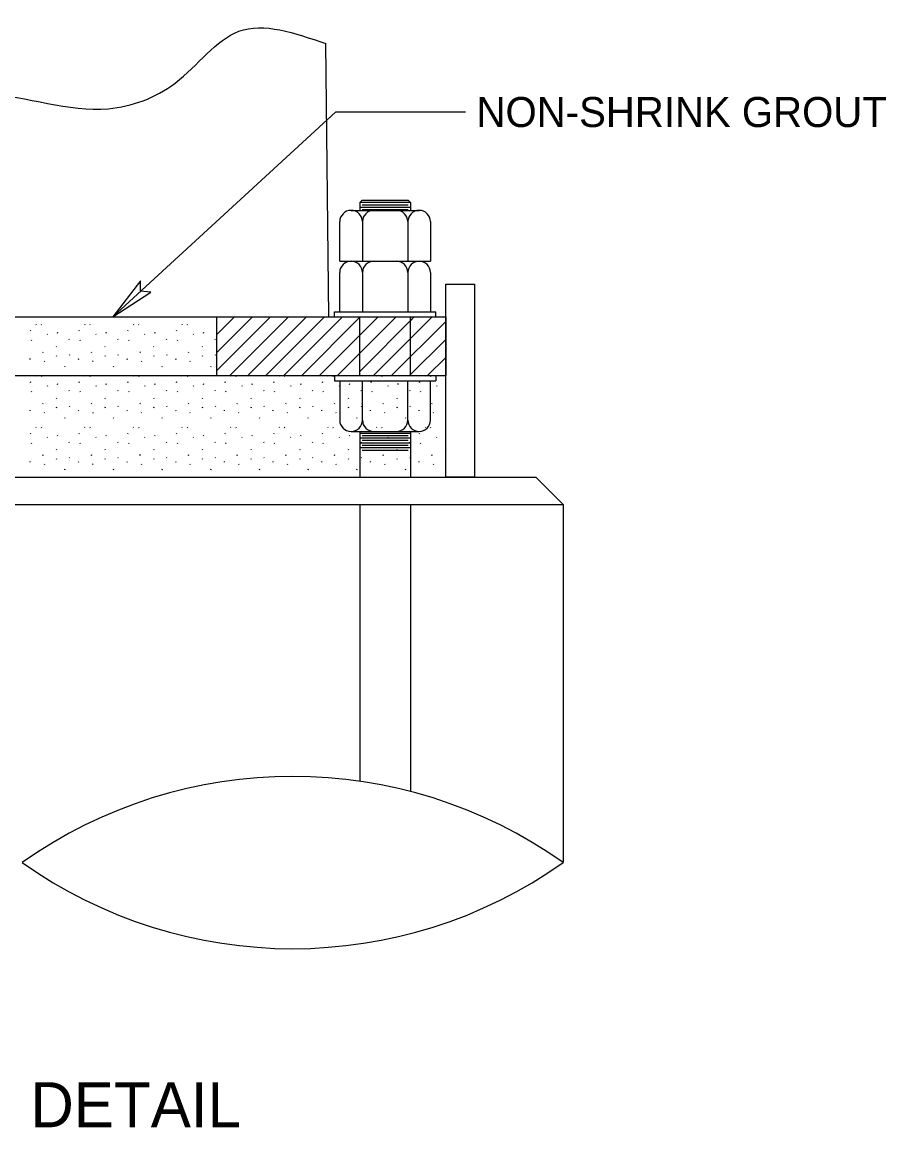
# Model space of a CAD drawing. Extents: x 99978 to 113378, y 99891 to 102182.
# Drawn here: x 111348.5 to 111693.8, y 100709.4 to 101151.3 of the extents above; entities that cross this region are included whole.
import ezdxf

# ---------------------------------------------------------------- set-up
doc = ezdxf.new("R2010")
doc.units = 0
doc.layers.add('Border Organizer Shape', color=7, linetype='Continuous')

msp = doc.modelspace()

# ---------------------------------------------------------------- linework, layer by layer
at = {"layer": 'Border Organizer Shape'}
for p, q in [((111471.07, 101033.49), (111469.85, 101142.75)), ((111473.79, 101115.41), (111384.79, 101033.49)), ((111525.69, 101115.41), (111473.79, 101115.41)), ((111484.44, 101080.15), (111483.47, 101079.18)), ((111483.47, 101079.18), (111483.47, 101076.09)), ((111503.75, 101079.18), (111483.47, 101079.18)), ((111484.44, 101080.15), (111502.78, 101080.15)), ((111502.78, 101078.2), (111484.44, 101078.2)), ((111503.75, 101079.18), (111502.78, 101080.15)), ((111503.75, 101079.18), (111503.75, 101076.09)), ((111479.98, 101076.09), (111507.24, 101076.09)), ((111503.75, 101077.23), (111483.47, 101077.23)), ((111502.78, 101076.26), (111484.44, 101076.26)), ((111475.47, 101055.81), (111475.47, 101071.59)), ((111484.54, 101071.59), (111484.54, 101055.81)), ((111502.68, 101071.59), (111502.68, 101055.81)), ((111511.74, 101071.59), (111511.74, 101055.81)), ((111475.47, 101055.81), (111511.74, 101055.81)), ((111479.98, 101055.81), (111507.24, 101055.81)), ((111475.47, 101035.52), (111475.47, 101051.3)), ((111484.54, 101051.3), (111484.54, 101035.52)), ((111502.68, 101051.3), (111502.68, 101035.52)), ((111511.74, 101051.3), (111511.74, 101035.52)), ((111473.32, 101035.52), (111513.89, 101035.52)), ((111473.32, 101033.49), (111473.32, 101035.52)), ((111475.47, 101035.52), (111511.74, 101035.52)), ((111513.89, 101033.49), (111513.89, 101035.52)), ((111179.13, 101033.49), (111517.82, 101033.49)), ((111354, 101030.62), (111354.14, 101030.41)), ((111356.08, 101030.54), (111356.22, 101030.32)), ((111373.44, 101030.62), (111373.59, 101030.41)), ((111375.52, 101030.54), (111375.67, 101030.32)), ((111392.89, 101030.62), (111393.03, 101030.41)), ((111394.97, 101030.54), (111395.12, 101030.32)), ((111412.33, 101030.62), (111412.48, 101030.41)), ((111414.42, 101030.54), (111414.56, 101030.32)), ((111426.19, 101033.49), (111426.19, 101033.49)), ((111426.19, 101026.31), (111433.37, 101033.49)), ((111426.19, 101019.12), (111440.56, 101033.49)), ((111426.19, 101011.93), (111447.75, 101033.49)), ((111426.19, 101033.49), (111426.19, 101010.06)), ((111431.5, 101010.06), (111454.94, 101033.49)), ((111438.69, 101010.06), (111462.12, 101033.49)), ((111445.87, 101010.06), (111469.31, 101033.49)), ((111453.06, 101010.06), (111476.5, 101033.49)), ((111460.25, 101010.06), (111483.68, 101033.49)), ((111467.43, 101010.06), (111490.87, 101033.49)), ((111473.32, 101033.49), (111513.89, 101033.49)), ((111474.62, 101010.06), (111498.06, 101033.49)), ((111505.25, 101033.49), (111483.47, 101011.72)), ((111483.47, 101010.06), (111483.47, 101033.49)), ((111489, 101010.06), (111512.43, 101033.49)), ((111496.18, 101010.06), (111517.82, 101031.7)), ((111503.75, 101032), (111505.25, 101033.49)), ((111503.75, 101010.06), (111503.75, 101033.49)), ((111517.82, 101033.49), (111517.82, 101010.06)), ((111351.84, 101027.91), (111351.99, 101028.24)), ((111358.53, 101026.65), (111358.68, 101026.43)), ((111362.62, 101027.07), (111362.77, 101027.4)), ((111371.29, 101027.91), (111371.43, 101028.24)), ((111377.98, 101026.65), (111378.12, 101026.43)), ((111382.07, 101027.07), (111382.21, 101027.4)), ((111390.73, 101027.91), (111390.88, 101028.24)), ((111397.42, 101026.65), (111397.57, 101026.43)), ((111401.51, 101027.07), (111401.66, 101027.4)), ((111410.18, 101027.91), (111410.32, 101028.24)), ((111416.87, 101026.65), (111417.01, 101026.43)), ((111420.96, 101027.07), (111421.11, 101027.4)), ((111352.07, 101024.34), (111352.21, 101024.12)), ((111362.14, 101021.74), (111362.28, 101021.52)), ((111367.19, 101024.74), (111367.34, 101024.52)), ((111371.51, 101024.34), (111371.66, 101024.12)), ((111381.58, 101021.74), (111381.73, 101021.52)), ((111386.64, 101024.74), (111386.78, 101024.52)), ((111390.96, 101024.34), (111391.1, 101024.12)), ((111401.03, 101021.74), (111401.17, 101021.52)), ((111406.08, 101024.74), (111406.23, 101024.52)), ((111410.4, 101024.34), (111410.55, 101024.12)), ((111420.47, 101021.74), (111420.62, 101021.52)), ((111425.53, 101024.74), (111425.68, 101024.52)), ((111503.37, 101010.06), (111517.82, 101024.51)), ((111351.5, 101016.87), (111351.54, 101016.54)), ((111356.7, 101019.29), (111356.85, 101019.62)), ((111362.26, 101017.79), (111362.4, 101018.12)), ((111367.33, 101018.5), (111367.47, 101018.28)), ((111370.95, 101016.87), (111370.98, 101016.54)), ((111376.15, 101019.29), (111376.29, 101019.62)), ((111381.7, 101017.79), (111381.85, 101018.12)), ((111386.77, 101018.5), (111386.92, 101018.28)), ((111390.39, 101016.87), (111390.43, 101016.54)), ((111395.59, 101019.29), (111395.74, 101019.62)), ((111401.15, 101017.79), (111401.29, 101018.12)), ((111406.22, 101018.5), (111406.37, 101018.28)), ((111409.84, 101016.87), (111409.88, 101016.54)), ((111415.04, 101019.29), (111415.18, 101019.62)), ((111420.59, 101017.79), (111420.74, 101018.12)), ((111425.67, 101018.5), (111425.81, 101018.28)), ((111510.56, 101010.06), (111517.82, 101017.32)), ((111357.23, 101015.9), (111357.38, 101015.68)), ((111365.58, 101013.55), (111365.73, 101013.88)), ((111376.68, 101015.9), (111376.82, 101015.68)), ((111385.03, 101013.55), (111385.18, 101013.88)), ((111396.12, 101015.9), (111396.27, 101015.68)), ((111404.48, 101013.55), (111404.62, 101013.88)), ((111415.57, 101015.9), (111415.72, 101015.68)), ((111423.92, 101013.55), (111424.07, 101013.88)), ((111270.76, 101010.06), (111426.19, 101010.06)), ((111351.84, 101007.35), (111351.99, 101007.68)), ((111354, 101010.06), (111354.14, 101009.84)), ((111356.08, 101009.97), (111356.22, 101009.75)), ((111371.29, 101007.35), (111371.43, 101007.68)), ((111373.44, 101010.06), (111373.59, 101009.84)), ((111375.52, 101009.97), (111375.67, 101009.75)), ((111390.73, 101007.35), (111390.88, 101007.68)), ((111392.89, 101010.06), (111393.03, 101009.84)), ((111394.97, 101009.97), (111395.12, 101009.75)), ((111410.18, 101007.35), (111410.32, 101007.68)), ((111412.33, 101010.06), (111412.48, 101009.84)), ((111414.42, 101009.97), (111414.56, 101009.75)), ((111426.19, 101010.06), (111517.82, 101010.06)), ((111429.62, 101007.35), (111429.77, 101007.68)), ((111431.78, 101010.06), (111431.93, 101009.84)), ((111433.86, 101009.97), (111434.01, 101009.75)), ((111441.84, 101010.06), (111517.82, 101010.06)), ((111449.07, 101007.35), (111449.22, 101007.68)), ((111451.23, 101010.06), (111451.37, 101009.84)), ((111453.31, 101009.97), (111453.45, 101009.75)), ((111468.52, 101007.35), (111468.66, 101007.68)), ((111470.67, 101010.06), (111470.82, 101009.84)), ((111472.75, 101009.97), (111472.9, 101009.75)), ((111473.32, 101010.06), (111513.89, 101010.06)), ((111473.32, 101010.06), (111473.32, 101008.03)), ((111473.32, 101008.03), (111513.89, 101008.03)), ((111475.47, 101008.03), (111511.74, 101008.03)), ((111475.47, 101008.03), (111475.47, 100992.25)), ((111484.54, 100992.25), (111484.54, 101008.03)), ((111487.96, 101007.35), (111488.11, 101007.68)), ((111490.12, 101010.06), (111490.27, 101009.84)), ((111492.2, 101009.97), (111492.35, 101009.75)), ((111502.68, 100992.25), (111502.68, 101008.03)), ((111507.41, 101007.35), (111507.55, 101007.68)), ((111509.57, 101010.06), (111509.71, 101009.84)), ((111511.65, 101009.97), (111511.79, 101009.75)), ((111511.74, 100992.25), (111511.74, 101008.03)), ((111513.89, 101010.06), (111513.89, 101008.03)), ((111517.74, 101010.06), (111517.82, 101010.14)), ((111352.07, 101003.77), (111352.21, 101003.55)), ((111358.53, 101006.08), (111358.68, 101005.86)), ((111362.62, 101006.51), (111362.77, 101006.84)), ((111367.19, 101004.17), (111367.34, 101003.95)), ((111371.51, 101003.77), (111371.66, 101003.55)), ((111377.98, 101006.08), (111378.12, 101005.86)), ((111382.07, 101006.51), (111382.21, 101006.84)), ((111386.64, 101004.17), (111386.78, 101003.95)), ((111390.96, 101003.77), (111391.1, 101003.55)), ((111397.42, 101006.08), (111397.57, 101005.86)), ((111401.51, 101006.51), (111401.66, 101006.84)), ((111406.08, 101004.17), (111406.23, 101003.95)), ((111410.4, 101003.77), (111410.55, 101003.55)), ((111416.87, 101006.08), (111417.01, 101005.86)), ((111420.96, 101006.51), (111421.11, 101006.84)), ((111425.53, 101004.17), (111425.68, 101003.95)), ((111429.85, 101003.77), (111430, 101003.55)), ((111436.31, 101006.08), (111436.46, 101005.86)), ((111440.41, 101006.51), (111440.55, 101006.84)), ((111444.98, 101004.17), (111445.12, 101003.95)), ((111449.3, 101003.77), (111449.44, 101003.55)), ((111455.76, 101006.08), (111455.91, 101005.86)), ((111459.85, 101006.51), (111460, 101006.84)), ((111464.42, 101004.17), (111464.57, 101003.95)), ((111468.74, 101003.77), (111468.89, 101003.55)), ((111475.21, 101006.08), (111475.35, 101005.86)), ((111479.3, 101006.51), (111479.44, 101006.84)), ((111483.87, 101004.17), (111484.01, 101003.95)), ((111488.19, 101003.77), (111488.33, 101003.55)), ((111494.65, 101006.08), (111494.8, 101005.86)), ((111498.74, 101006.51), (111498.89, 101006.84)), ((111503.31, 101004.17), (111503.46, 101003.95)), ((111507.63, 101003.77), (111507.78, 101003.55)), ((111514.1, 101006.08), (111514.25, 101005.86)), ((111356.7, 100998.72), (111356.85, 100999.05)), ((111362.14, 101001.18), (111362.28, 101000.96)), ((111376.15, 100998.72), (111376.29, 100999.05)), ((111381.58, 101001.18), (111381.73, 101000.96)), ((111395.59, 100998.72), (111395.74, 100999.05)), ((111401.03, 101001.18), (111401.17, 101000.96)), ((111415.04, 100998.72), (111415.18, 100999.05)), ((111420.47, 101001.18), (111420.62, 101000.96)), ((111434.48, 100998.72), (111434.63, 100999.05)), ((111439.92, 101001.18), (111440.07, 101000.96)), ((111453.93, 100998.72), (111454.08, 100999.05)), ((111459.37, 101001.18), (111459.51, 101000.96)), ((111473.38, 100998.72), (111473.52, 100999.05)), ((111478.81, 101001.18), (111478.96, 101000.96)), ((111492.82, 100998.72), (111492.97, 100999.05)), ((111498.26, 101001.18), (111498.41, 101000.96)), ((111512.27, 100998.72), (111512.42, 100999.05)), ((111517.71, 101001.18), (111517.82, 101001)), ((111351.5, 100996.3), (111351.54, 100995.97)), ((111357.23, 100995.33), (111357.38, 100995.11)), ((111362.26, 100997.22), (111362.4, 100997.55)), ((111367.33, 100997.93), (111367.47, 100997.71)), ((111370.95, 100996.3), (111370.98, 100995.97)), ((111376.68, 100995.33), (111376.82, 100995.11)), ((111381.7, 100997.22), (111381.85, 100997.55)), ((111386.77, 100997.93), (111386.92, 100997.71)), ((111390.39, 100996.3), (111390.43, 100995.97)), ((111396.12, 100995.33), (111396.27, 100995.11)), ((111401.15, 100997.22), (111401.29, 100997.55)), ((111406.22, 100997.93), (111406.37, 100997.71)), ((111409.84, 100996.3), (111409.88, 100995.97)), ((111415.57, 100995.33), (111415.72, 100995.11)), ((111420.59, 100997.22), (111420.74, 100997.55)), ((111425.67, 100997.93), (111425.81, 100997.71)), ((111429.29, 100996.3), (111429.32, 100995.97)), ((111435.02, 100995.33), (111435.16, 100995.11)), ((111440.04, 100997.22), (111440.19, 100997.55)), ((111445.11, 100997.93), (111445.26, 100997.71)), ((111448.73, 100996.3), (111448.77, 100995.97)), ((111454.46, 100995.33), (111454.61, 100995.11)), ((111459.49, 100997.22), (111459.63, 100997.55)), ((111464.56, 100997.93), (111464.71, 100997.71)), ((111468.18, 100996.3), (111468.21, 100995.97)), ((111473.91, 100995.33), (111474.05, 100995.11)), ((111478.93, 100997.22), (111479.08, 100997.55)), ((111484.01, 100997.93), (111484.15, 100997.71)), ((111487.62, 100996.3), (111487.66, 100995.97)), ((111493.35, 100995.33), (111493.5, 100995.11)), ((111498.38, 100997.22), (111498.53, 100997.55)), ((111503.45, 100997.93), (111503.6, 100997.71)), ((111507.07, 100996.3), (111507.11, 100995.97)), ((111512.8, 100995.33), (111512.95, 100995.11)), ((111365.58, 100992.98), (111365.73, 100993.31)), ((111385.03, 100992.98), (111385.18, 100993.31)), ((111404.48, 100992.98), (111404.62, 100993.31)), ((111423.92, 100992.98), (111424.07, 100993.31)), ((111443.37, 100992.98), (111443.51, 100993.31)), ((111462.81, 100992.98), (111462.96, 100993.31)), ((111482.26, 100992.98), (111482.41, 100993.31)), ((111501.71, 100992.98), (111501.85, 100993.31)), ((111351.84, 100986.78), (111351.99, 100987.11)), ((111354, 100989.49), (111354.14, 100989.27)), ((111356.08, 100989.41), (111356.22, 100989.19)), ((111358.53, 100985.51), (111358.68, 100985.29)), ((111362.62, 100985.94), (111362.77, 100986.27)), ((111371.29, 100986.78), (111371.43, 100987.11)), ((111373.44, 100989.49), (111373.59, 100989.27)), ((111375.52, 100989.41), (111375.67, 100989.19)), ((111377.98, 100985.51), (111378.12, 100985.29)), ((111382.07, 100985.94), (111382.21, 100986.27)), ((111390.73, 100986.78), (111390.88, 100987.11)), ((111392.89, 100989.49), (111393.03, 100989.27)), ((111394.97, 100989.41), (111395.12, 100989.19)), ((111397.42, 100985.51), (111397.57, 100985.29)), ((111401.51, 100985.94), (111401.66, 100986.27)), ((111410.18, 100986.78), (111410.32, 100987.11)), ((111412.33, 100989.49), (111412.48, 100989.27)), ((111414.42, 100989.41), (111414.56, 100989.19)), ((111416.87, 100985.51), (111417.01, 100985.29)), ((111420.96, 100985.94), (111421.11, 100986.27)), ((111429.62, 100986.78), (111429.77, 100987.11)), ((111431.78, 100989.49), (111431.93, 100989.27)), ((111433.86, 100989.41), (111434.01, 100989.19)), ((111436.31, 100985.51), (111436.46, 100985.29)), ((111440.41, 100985.94), (111440.55, 100986.27)), ((111449.07, 100986.78), (111449.22, 100987.11)), ((111451.23, 100989.49), (111451.37, 100989.27)), ((111453.31, 100989.41), (111453.45, 100989.19)), ((111455.76, 100985.51), (111455.91, 100985.29)), ((111459.85, 100985.94), (111460, 100986.27)), ((111468.52, 100986.78), (111468.66, 100987.11)), ((111470.67, 100989.49), (111470.82, 100989.27)), ((111472.75, 100989.41), (111472.9, 100989.19)), ((111475.21, 100985.51), (111475.35, 100985.29)), ((111479.3, 100985.94), (111479.44, 100986.27)), ((111479.98, 100987.74), (111507.24, 100987.74)), ((111483.47, 100987.74), (111483.47, 100969.49)), ((111503.75, 100986.97), (111483.47, 100986.97)), ((111502.78, 100986), (111484.44, 100986)), ((111487.96, 100986.78), (111488.11, 100987.11)), ((111490.12, 100989.49), (111490.27, 100989.27)), ((111492.2, 100989.41), (111492.35, 100989.19)), ((111494.65, 100985.51), (111494.8, 100985.29)), ((111498.74, 100985.94), (111498.89, 100986.27)), ((111503.75, 100987.74), (111503.75, 100969.49)), ((111507.41, 100986.78), (111507.55, 100987.11)), ((111509.57, 100989.49), (111509.71, 100989.27)), ((111511.65, 100989.41), (111511.79, 100989.19)), ((111514.1, 100985.51), (111514.25, 100985.29)), ((111352.07, 100983.2), (111352.21, 100982.98)), ((111367.19, 100983.6), (111367.34, 100983.38)), ((111371.51, 100983.2), (111371.66, 100982.98)), ((111386.64, 100983.6), (111386.78, 100983.38)), ((111390.96, 100983.2), (111391.1, 100982.98)), ((111406.08, 100983.6), (111406.23, 100983.38)), ((111410.4, 100983.2), (111410.55, 100982.98)), ((111425.53, 100983.6), (111425.68, 100983.38)), ((111429.85, 100983.2), (111430, 100982.98)), ((111444.98, 100983.6), (111445.12, 100983.38)), ((111449.3, 100983.2), (111449.44, 100982.98)), ((111464.42, 100983.6), (111464.57, 100983.38)), ((111468.74, 100983.2), (111468.89, 100982.98)), ((111503.75, 100985.03), (111483.47, 100985.03)), ((111503.75, 100983.08), (111483.47, 100983.08)), ((111503.75, 100981.13), (111483.47, 100981.13)), ((111483.87, 100983.6), (111484.01, 100983.38)), ((111502.78, 100984.05), (111484.44, 100984.05)), ((111502.78, 100982.1), (111484.44, 100982.1)), ((111488.19, 100983.2), (111488.33, 100982.98)), ((111503.31, 100983.6), (111503.46, 100983.38)), ((111507.63, 100983.2), (111507.78, 100982.98)), ((111356.7, 100978.15), (111356.85, 100978.48)), ((111362.14, 100980.61), (111362.28, 100980.39)), ((111362.26, 100976.65), (111362.4, 100976.98)), ((111367.33, 100977.36), (111367.47, 100977.14)), ((111376.15, 100978.15), (111376.29, 100978.48)), ((111381.58, 100980.61), (111381.73, 100980.39)), ((111381.7, 100976.65), (111381.85, 100976.98)), ((111386.77, 100977.36), (111386.92, 100977.14)), ((111395.59, 100978.15), (111395.74, 100978.48)), ((111401.03, 100980.61), (111401.17, 100980.39)), ((111401.15, 100976.65), (111401.29, 100976.98)), ((111406.22, 100977.36), (111406.37, 100977.14)), ((111415.04, 100978.15), (111415.18, 100978.48)), ((111420.47, 100980.61), (111420.62, 100980.39)), ((111420.59, 100976.65), (111420.74, 100976.98)), ((111425.67, 100977.36), (111425.81, 100977.14)), ((111434.48, 100978.15), (111434.63, 100978.48)), ((111439.92, 100980.61), (111440.07, 100980.39)), ((111440.04, 100976.65), (111440.19, 100976.98)), ((111445.11, 100977.36), (111445.26, 100977.14)), ((111453.93, 100978.15), (111454.08, 100978.48)), ((111459.37, 100980.61), (111459.51, 100980.39)), ((111459.49, 100976.65), (111459.63, 100976.98)), ((111464.56, 100977.36), (111464.71, 100977.14)), ((111473.38, 100978.15), (111473.52, 100978.48)), ((111478.81, 100980.61), (111478.96, 100980.39)), ((111478.93, 100976.65), (111479.08, 100976.98)), ((111484.01, 100977.36), (111484.15, 100977.14)), ((111502.78, 100980.16), (111484.44, 100980.16)), ((111492.82, 100978.15), (111492.97, 100978.48)), ((111498.26, 100980.61), (111498.41, 100980.39)), ((111498.38, 100976.65), (111498.53, 100976.98)), ((111503.45, 100977.36), (111503.6, 100977.14)), ((111512.27, 100978.15), (111512.42, 100978.48)), ((111517.71, 100980.61), (111517.82, 100980.43)), ((111351.5, 100975.74), (111351.54, 100975.41)), ((111357.23, 100974.77), (111357.38, 100974.55)), ((111365.58, 100972.41), (111365.73, 100972.74)), ((111370.95, 100975.74), (111370.98, 100975.41)), ((111376.68, 100974.77), (111376.82, 100974.55)), ((111385.03, 100972.41), (111385.18, 100972.74)), ((111390.39, 100975.74), (111390.43, 100975.41)), ((111396.12, 100974.77), (111396.27, 100974.55)), ((111404.48, 100972.41), (111404.62, 100972.74)), ((111409.84, 100975.74), (111409.88, 100975.41)), ((111415.57, 100974.77), (111415.72, 100974.55)), ((111423.92, 100972.41), (111424.07, 100972.74)), ((111429.29, 100975.74), (111429.32, 100975.41)), ((111435.02, 100974.77), (111435.16, 100974.55)), ((111443.37, 100972.41), (111443.51, 100972.74)), ((111448.73, 100975.74), (111448.77, 100975.41)), ((111454.46, 100974.77), (111454.61, 100974.55)), ((111462.81, 100972.41), (111462.96, 100972.74)), ((111468.18, 100975.74), (111468.21, 100975.41)), ((111473.91, 100974.77), (111474.05, 100974.55)), ((111482.26, 100972.41), (111482.41, 100972.74)), ((111487.62, 100975.74), (111487.66, 100975.41)), ((111493.35, 100974.77), (111493.5, 100974.55)), ((111501.71, 100972.41), (111501.85, 100972.74)), ((111507.07, 100975.74), (111507.11, 100975.41)), ((111512.8, 100974.77), (111512.95, 100974.55)), ((111143.07, 100969.49), (111553.88, 100969.49)), ((111179.13, 100969.49), (111517.82, 100969.49)), ((111553.88, 100969.49), (111564.82, 100958.55)), ((111132.13, 100958.55), (111564.82, 100958.55)), ((111483.47, 100958.55), (111483.47, 100847.9)), ((111503.75, 100958.55), (111503.75, 100843.81)), ((111564.82, 100958.55), (111564.82, 100815.41))]:
    msp.add_line(p, q, dxfattribs=at)
for points in [[(111395.8, 101047.91), (111384.79, 101033.49), (111399.95, 101043.47), (111395.82, 101043.78)], [(111529.31, 100969.49), (111517.82, 100969.49), (111517.82, 101046.6), (111529.31, 101046.6)]]:
    msp.add_lwpolyline(points, close=True, dxfattribs=at)
for centre, radius, start, end in [((111479.98, 101071.59), 4.51, 90, 180), ((111480.03, 101071.59), 4.51, 0, 90), ((111489.05, 101071.59), 4.51, 90, 180), ((111498.17, 101071.59), 4.51, 0, 90), ((111507.18, 101071.59), 4.51, 90, 180), ((111507.24, 101071.59), 4.51, 0, 90), ((111479.98, 101051.3), 4.51, 90, 180), ((111480.03, 101051.3), 4.51, 0, 90), ((111489.05, 101051.3), 4.51, 90, 180), ((111498.17, 101051.3), 4.51, 0, 90), ((111507.18, 101051.3), 4.51, 90, 180), ((111507.24, 101051.3), 4.51, 0, 90), ((111479.98, 100992.25), 4.51, 180, 270), ((111480.03, 100992.25), 4.51, 270, 0), ((111489.05, 100992.25), 4.51, 180, 270), ((111498.17, 100992.25), 4.51, 270, 0), ((111507.18, 100992.25), 4.51, 180, 270), ((111507.24, 100992.25), 4.51, 270, 0), ((111456.65, 100662.67), 187.16, 54.6933, 125.3067), ((111456.65, 100968.15), 187.16, 234.6933, 305.3067)]:
    msp.add_arc(centre, radius, start, end, dxfattribs=at)
msp.add_spline([(111227.24, 101142.84), (111255.66, 101145.5), (111278.24, 101129.09), (111333.74, 101122.92), (111382.99, 101116.75), (111409.66, 101127.01), (111435.16, 101147.71), (111469.85, 101142.75)], degree=3, dxfattribs=at)

# ---------------------------------------------------------------- texts
for s, height, p in [(' NON-SHRINK GROUT', 12, (111525.69, 101109.41)), ('GROUTING DETAIL', 18, (111215.36, 100709.61))]:
    msp.add_text(s, height=height, dxfattribs=at).set_placement(p)

doc.saveas('drawing.dxf')
